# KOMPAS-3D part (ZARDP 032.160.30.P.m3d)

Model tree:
1. Булева операция:7
2. Булева операция:8
3. Булева операция:9
4. Булева операция:10
5. Булева операция:11
6. Булева операция:12

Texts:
  ООО ИК Энерпред-Ярдос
